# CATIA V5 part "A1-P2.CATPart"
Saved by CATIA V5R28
Part number: Part2
Source: Unknown
Bounding box of the stored display mesh (mm): x -20 to 20, y -19.988 to 19.953, z -35 to 35
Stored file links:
  E:\TP Catia - Documents\Additional Exercise\Contrôle\Problem-3-Section-J\A1-P2.CATPart
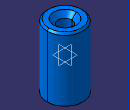
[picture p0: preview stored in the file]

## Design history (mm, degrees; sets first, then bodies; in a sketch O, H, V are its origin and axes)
Body1 (main body)
  Solid1 "Corps principal": solid without history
